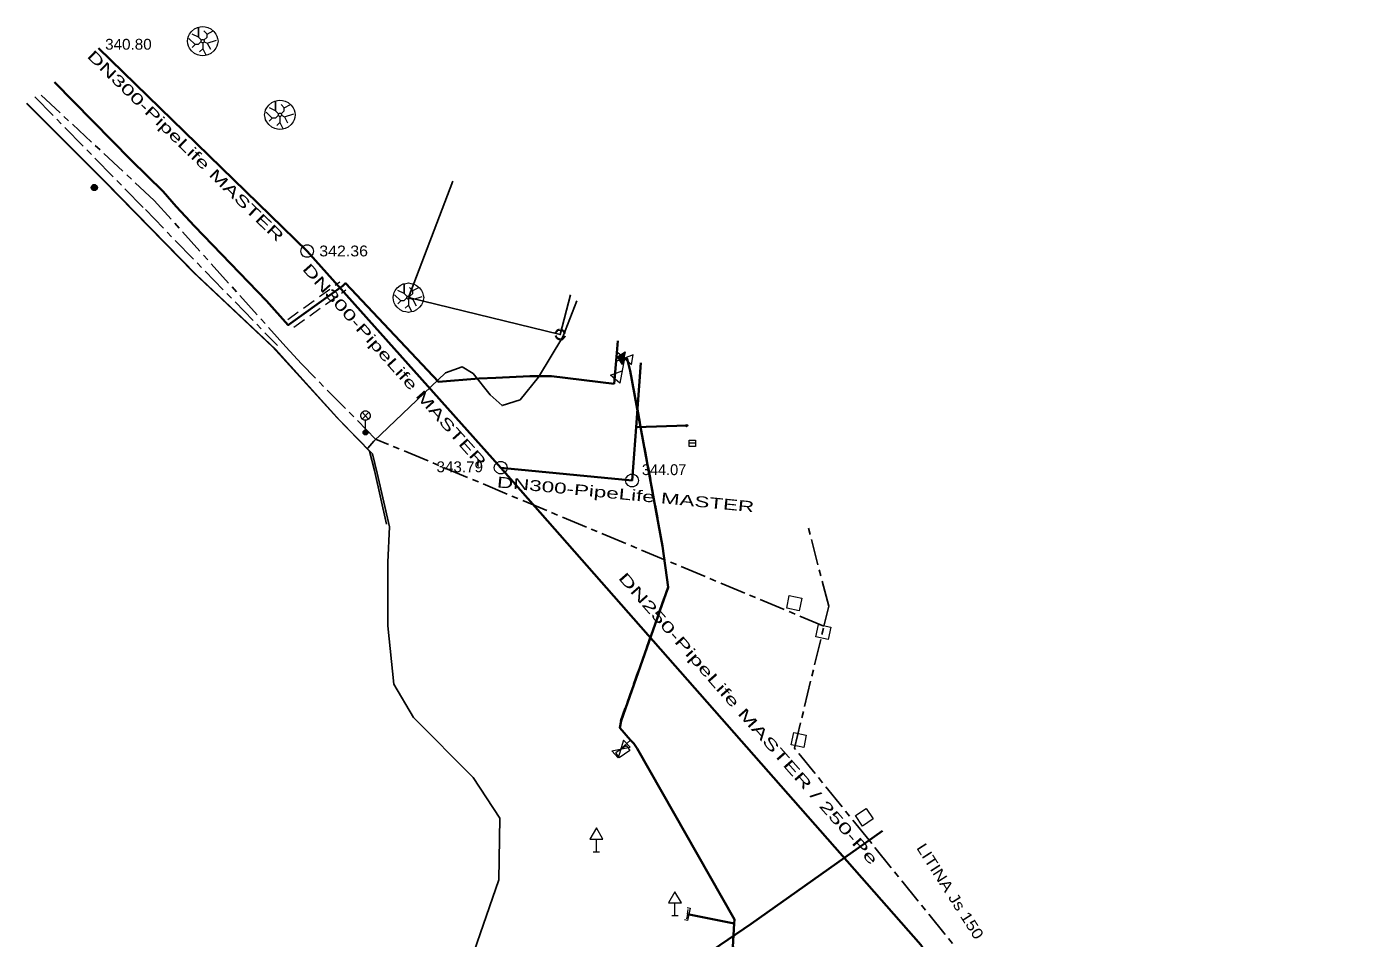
# Model space of a CAD drawing. Extents: x -763495 to -763378, y -1031793 to -1031652.
# Drawn here: x -763495.2 to -763391.6, y -1031723.9 to -1031652.3 of the extents above; entities that cross this region are included whole.
import ezdxf
from ezdxf.enums import TextEntityAlignment as Align

# ---------------------------------------------------------------- set-up
doc = ezdxf.new("R2010")
doc.units = 0
doc.header["$LTSCALE"] = 0.34
doc.linetypes.add('LONG_DASH_SHORT_DASH', pattern=[9.9, 6, -1.2, 1.5, -1.2])
doc.linetypes.add('MEDIUM_DASHED', pattern=[4.5, 3, -1.5])
for name, color, linetype, lineweight in [('23', 7, 'Continuous', 13), ('27', 7, 'Continuous', 13), ('33', 7, 'Continuous', 13), ('34', 7, 'Continuous', 13), ('35', 7, 'Continuous', 13), ('37', 7, 'Continuous', 13), ('40', 7, 'Continuous', 13), ('41', 7, 'Continuous', 13), ('43', 7, 'Continuous', 25), ('44', 7, 'Continuous', 35), ('45', 7, 'Continuous', 13), ('48', 7, 'Continuous', 25), ('51', 7, 'LONG_DASH_SHORT_DASH', 25), ('53', 7, 'Continuous', 25)]:
    doc.layers.add(name, color=color, linetype=linetype, lineweight=lineweight)

msp = doc.modelspace()

# ---------------------------------------------------------------- linework, layer by layer
at = {"layer": '23'}
for p, q in [((-763450.74, -1031717.13), (-763450.24, -1031717.13)), ((-763444.57, -1031722.14), (-763444.07, -1031722.14))]:
    msp.add_line(p, q, dxfattribs=at)
for points in [[(-763450.49, -1031717.13), (-763450.49, -1031716.13), (-763449.99, -1031716.13), (-763450.49, -1031715.255), (-763450.99, -1031716.13), (-763450.49, -1031716.13)], [(-763444.32, -1031722.14), (-763444.32, -1031721.14), (-763443.82, -1031721.14), (-763444.32, -1031720.265), (-763444.82, -1031721.14), (-763444.32, -1031721.14)]]:
    msp.add_lwpolyline(points, dxfattribs=at)
at = {"layer": '27'}
for p, q in [((-763481.04, -1031652.94), (-763481.28, -1031652.7)), ((-763481.98, -1031653.76), (-763482.22, -1031654)), ((-763481.38, -1031654.1), (-763481.14, -1031654.58)), ((-763481.02, -1031653.66), (-763480.3, -1031653.42)), ((-763474.98, -1031658.72), (-763475.22, -1031658.48)), ((-763474.96, -1031659.44), (-763474.24, -1031659.2)), ((-763475.92, -1031659.54), (-763476.16, -1031659.78)), ((-763475.32, -1031659.88), (-763475.08, -1031660.36)), ((-763464.9, -1031673.07), (-763465.14, -1031672.83)), ((-763464.88, -1031673.79), (-763464.16, -1031673.55)), ((-763465.84, -1031673.89), (-763466.08, -1031674.13)), ((-763465.24, -1031674.23), (-763465, -1031674.71)), ((-763453.615, -1031676.44), (-763453.75, -1031676.38)), ((-763453.615, -1031676.62), (-763453.75, -1031676.68)), ((-763453.585, -1031676.38), (-763453.705, -1031676.305)), ((-763453.585, -1031676.68), (-763453.705, -1031676.755)), ((-763453.54, -1031676.32), (-763453.645, -1031676.215)), ((-763453.54, -1031676.74), (-763453.645, -1031676.845)), ((-763453.495, -1031676.275), (-763453.57, -1031676.14)), ((-763453.495, -1031676.785), (-763453.57, -1031676.92)), ((-763453.435, -1031676.245), (-763453.48, -1031676.095)), ((-763453.435, -1031676.815), (-763453.48, -1031676.965)), ((-763453.375, -1031676.23), (-763453.405, -1031676.08)), ((-763453.375, -1031676.83), (-763453.405, -1031676.98)), ((-763453.285, -1031676.23), (-763453.255, -1031676.08)), ((-763453.285, -1031676.83), (-763453.255, -1031676.98)), ((-763453.225, -1031676.245), (-763453.18, -1031676.095)), ((-763453.225, -1031676.815), (-763453.18, -1031676.965)), ((-763453.165, -1031676.275), (-763453.09, -1031676.14)), ((-763453.165, -1031676.785), (-763453.09, -1031676.92)), ((-763453.12, -1031676.32), (-763453.015, -1031676.215)), ((-763453.12, -1031676.74), (-763453.015, -1031676.845)), ((-763453.075, -1031676.38), (-763452.955, -1031676.305)), ((-763453.075, -1031676.68), (-763452.955, -1031676.755)), ((-763453.045, -1031676.44), (-763452.91, -1031676.38)), ((-763453.045, -1031676.62), (-763452.91, -1031676.68))]:
    msp.add_line(p, q, dxfattribs=at)
for points in [[(-763482.58, -1031653.5), (-763482.54, -1031653.3), (-763482.5, -1031653.1), (-763482.42, -1031652.94), (-763482.26, -1031652.74), (-763482.02, -1031652.54), (-763481.78, -1031652.42), (-763481.58, -1031652.38), (-763481.38, -1031652.34), (-763481.18, -1031652.38), (-763480.98, -1031652.42), (-763480.74, -1031652.54), (-763480.5, -1031652.74), (-763480.34, -1031652.94), (-763480.26, -1031653.1), (-763480.22, -1031653.3), (-763480.18, -1031653.5), (-763480.22, -1031653.7), (-763480.26, -1031653.9), (-763480.34, -1031654.06), (-763480.5, -1031654.26), (-763480.74, -1031654.46), (-763480.98, -1031654.58), (-763481.18, -1031654.62), (-763481.38, -1031654.66), (-763481.58, -1031654.62), (-763481.78, -1031654.58), (-763482.02, -1031654.46), (-763482.26, -1031654.26), (-763482.42, -1031654.06), (-763482.5, -1031653.9), (-763482.54, -1031653.7)], [(-763481.5, -1031653.5), (-763481.5, -1031653.46), (-763481.48, -1031653.42), (-763481.42, -1031653.38), (-763481.34, -1031653.38), (-763481.28, -1031653.42), (-763481.26, -1031653.46), (-763481.26, -1031653.54), (-763481.28, -1031653.58), (-763481.34, -1031653.62), (-763481.42, -1031653.62), (-763481.48, -1031653.58), (-763481.5, -1031653.54)], [(-763476.52, -1031659.28), (-763476.48, -1031659.08), (-763476.44, -1031658.88), (-763476.36, -1031658.72), (-763476.2, -1031658.52), (-763475.96, -1031658.32), (-763475.72, -1031658.2), (-763475.52, -1031658.16), (-763475.32, -1031658.12), (-763475.12, -1031658.16), (-763474.92, -1031658.2), (-763474.68, -1031658.32), (-763474.44, -1031658.52), (-763474.28, -1031658.72), (-763474.2, -1031658.88), (-763474.16, -1031659.08), (-763474.12, -1031659.28), (-763474.16, -1031659.48), (-763474.2, -1031659.68), (-763474.28, -1031659.84), (-763474.44, -1031660.04), (-763474.68, -1031660.24), (-763474.92, -1031660.36), (-763475.12, -1031660.4), (-763475.32, -1031660.44), (-763475.52, -1031660.4), (-763475.72, -1031660.36), (-763475.96, -1031660.24), (-763476.2, -1031660.04), (-763476.36, -1031659.84), (-763476.44, -1031659.68), (-763476.48, -1031659.48)], [(-763475.44, -1031659.28), (-763475.44, -1031659.24), (-763475.42, -1031659.2), (-763475.36, -1031659.16), (-763475.28, -1031659.16), (-763475.22, -1031659.2), (-763475.2, -1031659.24), (-763475.2, -1031659.32), (-763475.22, -1031659.36), (-763475.28, -1031659.4), (-763475.36, -1031659.4), (-763475.42, -1031659.36), (-763475.44, -1031659.32)], [(-763466.44, -1031673.63), (-763466.4, -1031673.43), (-763466.36, -1031673.23), (-763466.28, -1031673.07), (-763466.12, -1031672.87), (-763465.88, -1031672.67), (-763465.64, -1031672.55), (-763465.44, -1031672.51), (-763465.24, -1031672.47), (-763465.04, -1031672.51), (-763464.84, -1031672.55), (-763464.6, -1031672.67), (-763464.36, -1031672.87), (-763464.2, -1031673.07), (-763464.12, -1031673.23), (-763464.08, -1031673.43), (-763464.04, -1031673.63), (-763464.08, -1031673.83), (-763464.12, -1031674.03), (-763464.2, -1031674.19), (-763464.36, -1031674.39), (-763464.6, -1031674.59), (-763464.84, -1031674.71), (-763465.04, -1031674.75), (-763465.24, -1031674.79), (-763465.44, -1031674.75), (-763465.64, -1031674.71), (-763465.88, -1031674.59), (-763466.12, -1031674.39), (-763466.28, -1031674.19), (-763466.36, -1031674.03), (-763466.4, -1031673.83)], [(-763465.36, -1031673.63), (-763465.36, -1031673.59), (-763465.34, -1031673.55), (-763465.28, -1031673.51), (-763465.2, -1031673.51), (-763465.14, -1031673.55), (-763465.12, -1031673.59), (-763465.12, -1031673.67), (-763465.14, -1031673.71), (-763465.2, -1031673.75), (-763465.28, -1031673.75), (-763465.34, -1031673.71), (-763465.36, -1031673.67)]]:
    msp.add_lwpolyline(points, close=True, dxfattribs=at)
for points in [[(-763481.48, -1031653.42), (-763481.72, -1031653.18), (-763481.72, -1031652.46), (-763481.72, -1031653.18), (-763482.2, -1031652.94)], [(-763481.28, -1031653.42), (-763481.04, -1031653.18), (-763481.04, -1031652.94), (-763480.56, -1031652.7)], [(-763481.5, -1031653.52), (-763481.74, -1031653.76), (-763481.98, -1031653.76), (-763482.46, -1031653.28)], [(-763481.38, -1031653.62), (-763481.38, -1031654.1), (-763481.62, -1031654.34)], [(-763481.26, -1031653.54), (-763481.02, -1031653.66), (-763480.78, -1031654.14)], [(-763475.42, -1031659.2), (-763475.66, -1031658.96), (-763475.66, -1031658.24), (-763475.66, -1031658.96), (-763476.14, -1031658.72)], [(-763475.44, -1031659.3), (-763475.68, -1031659.54), (-763475.92, -1031659.54), (-763476.4, -1031659.06)], [(-763475.22, -1031659.2), (-763474.98, -1031658.96), (-763474.98, -1031658.72), (-763474.5, -1031658.48)], [(-763475.2, -1031659.32), (-763474.96, -1031659.44), (-763474.72, -1031659.92)], [(-763475.32, -1031659.4), (-763475.32, -1031659.88), (-763475.56, -1031660.12)], [(-763465.34, -1031673.55), (-763465.58, -1031673.31), (-763465.58, -1031672.59), (-763465.58, -1031673.31), (-763466.06, -1031673.07)], [(-763465.36, -1031673.65), (-763465.6, -1031673.89), (-763465.84, -1031673.89), (-763466.32, -1031673.41)], [(-763465.24, -1031673.75), (-763465.24, -1031674.23), (-763465.48, -1031674.47)], [(-763465.14, -1031673.55), (-763464.9, -1031673.31), (-763464.9, -1031673.07), (-763464.42, -1031672.83)], [(-763465.12, -1031673.67), (-763464.88, -1031673.79), (-763464.64, -1031674.27)], [(-763453.345, -1031676.53), (-763453.315, -1031676.53), (-763453.33, -1031676.53)]]:
    msp.add_lwpolyline(points, dxfattribs=at)
at = {"layer": '27', "lineweight": 25}
msp.add_lwpolyline([(-763452.509, -1031673.421), (-763453.33, -1031676.53), (-763465.24, -1031673.63), (-763461.749, -1031664.479)], dxfattribs=at)
at = {"layer": '33'}
for points in [[(-763435.556, -1031698.001), (-763435.35, -1031697.023), (-763434.371, -1031697.229), (-763434.578, -1031698.207)], [(-763433.275, -1031700.265), (-763433.068, -1031699.286), (-763432.09, -1031699.493), (-763432.296, -1031700.471)], [(-763435.2, -1031708.737), (-763434.993, -1031707.758), (-763434.015, -1031707.965), (-763434.221, -1031708.943)], [(-763430.16, -1031714.277), (-763429.327, -1031713.724), (-763428.774, -1031714.556), (-763429.606, -1031715.11)]]:
    msp.add_lwpolyline(points, close=True, dxfattribs=at)
at = {"layer": '34'}
for points in [[(-763473.074, -1031669.495), (-763472.874, -1031669.59), (-763472.734, -1031669.765), (-763472.684, -1031669.98), (-763472.734, -1031670.195), (-763472.874, -1031670.37), (-763473.074, -1031670.465), (-763473.299, -1031670.465), (-763473.499, -1031670.37), (-763473.639, -1031670.195), (-763473.689, -1031669.98), (-763473.639, -1031669.765), (-763473.499, -1031669.59), (-763473.299, -1031669.495)], [(-763443.473, -1031683.621), (-763443.395, -1031683.582), (-763443.323, -1031683.633), (-763443.331, -1031683.723), (-763443.409, -1031683.762), (-763443.48, -1031683.711)], [(-763457.885, -1031686.496), (-763457.685, -1031686.591), (-763457.545, -1031686.766), (-763457.495, -1031686.981), (-763457.545, -1031687.196), (-763457.685, -1031687.371), (-763457.885, -1031687.466), (-763458.11, -1031687.466), (-763458.31, -1031687.371), (-763458.45, -1031687.196), (-763458.5, -1031686.981), (-763458.45, -1031686.766), (-763458.31, -1031686.591), (-763458.11, -1031686.496)], [(-763447.576, -1031687.501), (-763447.376, -1031687.596), (-763447.236, -1031687.771), (-763447.186, -1031687.986), (-763447.236, -1031688.201), (-763447.376, -1031688.376), (-763447.576, -1031688.471), (-763447.801, -1031688.471), (-763448.001, -1031688.376), (-763448.141, -1031688.201), (-763448.191, -1031687.986), (-763448.141, -1031687.771), (-763448.001, -1031687.596), (-763447.801, -1031687.501)]]:
    msp.add_lwpolyline(points, close=True, dxfattribs=at)
at = {"layer": '35'}
for points in [[(-763447.738, -1031678.869), (-763447.603, -1031678.131), (-763448.967, -1031678.643), (-763448.832, -1031677.905)], [(-763447.845, -1031708.914), (-763448.351, -1031708.361), (-763448.767, -1031709.759), (-763449.273, -1031709.206)]]:
    msp.add_lwpolyline(points, close=True, dxfattribs=at)
msp.add_lwpolyline([(-763448.285, -1031678.387), (-763448.646, -1031680.354), (-763449.392, -1031679.709), (-763448.466, -1031679.371)], dxfattribs=at)
at = {"layer": '37'}
msp.add_lwpolyline([(-763489.965, -1031664.76), (-763489.81, -1031664.76), (-763489.685, -1031664.85), (-763489.635, -1031664.995), (-763489.685, -1031665.14), (-763489.81, -1031665.23), (-763489.965, -1031665.23), (-763490.09, -1031665.14), (-763490.14, -1031664.995), (-763490.09, -1031664.85), (-763489.965, -1031664.76), (-763489.95, -1031664.78), (-763489.83, -1031664.78), (-763489.75, -1031664.82), (-763490.03, -1031664.82), (-763490.07, -1031664.86), (-763489.71, -1031664.86), (-763489.71, -1031664.9), (-763490.07, -1031664.9), (-763490.09, -1031664.94), (-763489.69, -1031664.94), (-763489.67, -1031664.98), (-763490.11, -1031664.98), (-763490.11, -1031665.02), (-763489.67, -1031665.02), (-763489.685, -1031665.06), (-763490.09, -1031665.06), (-763490.085, -1031665.1), (-763489.68, -1031665.1), (-763489.705, -1031665.14), (-763490.065, -1031665.14), (-763490.025, -1031665.18), (-763489.745, -1031665.18), (-763489.8, -1031665.22), (-763489.97, -1031665.22)], dxfattribs=at)
at = {"layer": '40'}
for p, q in [((-763468.36, -1031683.17), (-763468.875, -1031682.63)), ((-763468.87, -1031683.16), (-763468.345, -1031682.63))]:
    msp.add_line(p, q, dxfattribs=at)
for points in [[(-763468.615, -1031684.035), (-763468.615, -1031683.4), (-763468.615, -1031683.255), (-763468.71, -1031683.255), (-763468.875, -1031683.16), (-763468.975, -1031682.99), (-763468.975, -1031682.795), (-763468.88, -1031682.625), (-763468.71, -1031682.53), (-763468.515, -1031682.53), (-763468.345, -1031682.625), (-763468.25, -1031682.795), (-763468.25, -1031682.99), (-763468.36, -1031683.17), (-763468.515, -1031683.255), (-763468.61, -1031683.255)], [(-763468.61, -1031684.035), (-763468.535, -1031684.035), (-763468.425, -1031684.145), (-763468.425, -1031684.3), (-763468.535, -1031684.41), (-763468.69, -1031684.41), (-763468.8, -1031684.3), (-763468.8, -1031684.145), (-763468.69, -1031684.035), (-763468.615, -1031684.035), (-763468.54, -1031684.055), (-763468.69, -1031684.055), (-763468.72, -1031684.08), (-763468.52, -1031684.08), (-763468.48, -1031684.12), (-763468.76, -1031684.12), (-763468.78, -1031684.16), (-763468.455, -1031684.16), (-763468.455, -1031684.2), (-763468.78, -1031684.2), (-763468.78, -1031684.24), (-763468.455, -1031684.24), (-763468.455, -1031684.28), (-763468.775, -1031684.28), (-763468.755, -1031684.32), (-763468.475, -1031684.32), (-763468.515, -1031684.36), (-763468.715, -1031684.36), (-763468.69, -1031684.38), (-763468.535, -1031684.38)]]:
    msp.add_lwpolyline(points, dxfattribs=at)
at = {"layer": '41'}
msp.add_lwpolyline([(-763442.72, -1031685.06), (-763442.72, -1031685.31), (-763443.22, -1031685.31), (-763443.22, -1031684.81), (-763442.72, -1031684.81), (-763442.72, -1031685.06), (-763443.22, -1031685.06)], dxfattribs=at)
at = {"layer": '43', "linetype": 'LONG_DASH_SHORT_DASH'}
for points in [[(-763410.479, -1031739.762), (-763410.419, -1031739.329), (-763429.088, -1031716.231), (-763434.935, -1031708.998), (-763432.635, -1031699.413), (-763467.811, -1031684.74), (-763473.63, -1031678.84), (-763474.846, -1031677.495), (-763485.18, -1031666.004), (-763494.195, -1031657.611)], [(-763432.635, -1031699.413), (-763432.255, -1031697.852), (-763433.93, -1031691.402)]]:
    msp.add_lwpolyline(points, dxfattribs=at)
at = {"layer": '43', "lineweight": 35}
msp.add_lwpolyline([(-763428.03, -1031715.48), (-763438.34, -1031722.78), (-763475.986, -1031748.441)], dxfattribs=at)
at = {"layer": '44'}
msp.add_line((-763443.402, -1031683.672), (-763447.378, -1031683.808), dxfattribs=at)
for points in [[(-763457.995, -1031686.981), (-763473.184, -1031669.98), (-763489.553, -1031654.06)], [(-763447.005, -1031678.748), (-763447.378, -1031683.808), (-763447.686, -1031687.986), (-763457.995, -1031686.981)], [(-763391.618, -1031789.234), (-763393.492, -1031784.483), (-763400.133, -1031767.646), (-763400.737, -1031766.222), (-763405.172, -1031755.763), (-763407.519, -1031750.23), (-763407.897, -1031749.337), (-763411.012, -1031744.81), (-763417.435, -1031735.477), (-763425.031, -1031724.437), (-763457.995, -1031686.981)]]:
    msp.add_lwpolyline(points, dxfattribs=at)
at = {"layer": '45', "linetype": 'MEDIUM_DASHED'}
for p, q in [((-763474.704, -1031675.347), (-763470.615, -1031672.388)), ((-763474.474, -1031675.633), (-763470.383, -1031672.702)), ((-763474.223, -1031675.947), (-763470.146, -1031673.022)), ((-763447.879, -1031679.397), (-763445.339, -1031693.147)), ((-763447.84, -1031679.39), (-763445.3, -1031693.14)), ((-763447.801, -1031679.383), (-763445.261, -1031693.133)), ((-763448.588, -1031706.827), (-763444.887, -1031696.347)), ((-763448.55, -1031706.84), (-763444.849, -1031696.36)), ((-763448.512, -1031706.853), (-763444.811, -1031696.373))]:
    msp.add_line(p, q, dxfattribs=at)
at = {"layer": '45', "lineweight": 35}
for p, q in [((-763448.909, -1031678.28), (-763448.795, -1031677.015)), ((-763449.1, -1031680.39), (-763448.909, -1031678.28)), ((-763443.35, -1031722.02), (-763439.677, -1031722.759))]:
    msp.add_line(p, q, dxfattribs=at)
at = {"layer": '45', "lineweight": 25}
msp.add_line((-763447.81, -1031708.37), (-763448.559, -1031709.06), dxfattribs=at)
at = {"layer": '45'}
for q in [(-763443.425, -1031722.388), (-763443.275, -1031721.652)]:
    msp.add_line((-763443.35, -1031722.02), q, dxfattribs=at)
at = {"layer": '45', "lineweight": 35}
for points in [[(-763493.013, -1031656.707), (-763486.99, -1031662.84), (-763484.47, -1031665.3), (-763483.46, -1031666.48), (-763482.73, -1031667.26), (-763482.02, -1031668.02), (-763476.37, -1031673.88), (-763474.67, -1031675.79), (-763474.47, -1031675.63), (-763470.383, -1031672.702), (-763470.17, -1031672.5), (-763462.89, -1031680.24), (-763459.7, -1031679.97), (-763458.38, -1031679.94), (-763455.7, -1031679.8), (-763454, -1031679.8), (-763449.1, -1031680.39)], [(-763448.587, -1031678.33), (-763448.597, -1031678.328), (-763448.857, -1031678.285), (-763448.909, -1031678.28)], [(-763439.677, -1031722.759), (-763439.66, -1031722.45), (-763447.3, -1031709.02), (-763447.56, -1031708.63), (-763447.81, -1031708.37), (-763448.65, -1031707.4), (-763448.55, -1031706.84), (-763444.849, -1031696.36), (-763445.3, -1031693.14), (-763447.84, -1031679.39), (-763448.072, -1031678.425), (-763448.285, -1031678.387), (-763448.587, -1031678.33)], [(-763414.95, -1031744.87), (-763415.97, -1031743.05), (-763420.26, -1031739.42), (-763424.39, -1031735.42), (-763434.3, -1031728.54), (-763439.78, -1031724.58), (-763439.677, -1031722.759)]]:
    msp.add_lwpolyline(points, dxfattribs=at)
at = {"layer": '45'}
for points in [[(-763448.442, -1031678.87), (-763448.832, -1031678.28), (-763448.242, -1031677.89), (-763448.369, -1031678.512), (-763448.442, -1031678.87), (-763448.459, -1031678.8), (-763448.331, -1031678.178), (-763448.283, -1031677.943), (-763448.331, -1031677.974), (-763448.458, -1031678.596), (-763448.491, -1031678.758), (-763448.523, -1031678.716), (-763448.396, -1031678.093), (-763448.378, -1031678.005), (-763448.426, -1031678.041), (-763448.553, -1031678.664), (-763448.585, -1031678.621), (-763448.475, -1031678.082), (-763448.521, -1031678.109), (-763448.616, -1031678.574), (-763448.648, -1031678.527), (-763448.568, -1031678.135), (-763448.616, -1031678.171), (-763448.68, -1031678.485), (-763448.711, -1031678.437), (-763448.665, -1031678.212), (-763448.706, -1031678.239), (-763448.738, -1031678.396), (-763448.769, -1031678.349), (-763448.753, -1031678.27), (-763448.801, -1031678.302)], [(-763443.373, -1031721.505), (-763443.128, -1031721.555), (-763443.327, -1031722.535), (-763443.572, -1031722.485)]]:
    msp.add_lwpolyline(points, dxfattribs=at)
msp.add_lwpolyline([(-763448.559, -1031709.06), (-763448.147, -1031708.777), (-763447.864, -1031709.189), (-763448.688, -1031709.755), (-763448.971, -1031709.343)], close=True, dxfattribs=at)
at = {"layer": '48'}
for p, q in [((-763453.12, -1031676.72), (-763453.119, -1031676.72)), ((-763462.33, -1031679.54), (-763462.329, -1031679.54)), ((-763461.03, -1031679.07), (-763461.029, -1031679.07)), ((-763460.17, -1031679.58), (-763460.169, -1031679.58)), ((-763455.03, -1031679.88), (-763455.029, -1031679.88)), ((-763458.82, -1031681.25), (-763458.819, -1031681.25)), ((-763457.89, -1031682.1), (-763457.889, -1031682.1)), ((-763456.48, -1031681.65), (-763456.479, -1031681.65)), ((-763468.42, -1031685.45), (-763467.95, -1031684.91)), ((-763467.95, -1031684.91), (-763467.949, -1031684.91)), ((-763468.42, -1031685.45), (-763468.419, -1031685.45))]:
    msp.add_line(p, q, dxfattribs=at)
for points in [[(-763495.215, -1031658.392), (-763489.14, -1031664.47), (-763482.1, -1031671.65), (-763475.9, -1031677.49), (-763470.84, -1031683.08), (-763468.28, -1031685.69), (-763467.9, -1031687.2), (-763466.95, -1031691.41)], [(-763495.174, -1031658.36), (-763488.91, -1031664.64), (-763481.87, -1031671.83)], [(-763481.87, -1031671.83), (-763475.67, -1031677.68), (-763470.62, -1031683.28), (-763468.06, -1031685.9), (-763467.68, -1031687.41), (-763466.73, -1031691.62), (-763466.86, -1031694.4), (-763466.86, -1031699.4)], [(-763467.95, -1031684.91), (-763462.33, -1031679.54), (-763461.03, -1031679.07), (-763460.17, -1031679.58), (-763458.82, -1031681.25), (-763457.89, -1031682.1), (-763456.48, -1031681.65), (-763455.03, -1031679.88), (-763453.12, -1031676.72), (-763452.034, -1031673.881)], [(-763466.86, -1031699.4), (-763466.38, -1031703.98), (-763464.85, -1031706.59), (-763460.17, -1031711.3), (-763458.07, -1031714.49), (-763458.15, -1031719.33)], [(-763458.15, -1031719.33), (-763461.3, -1031728.5), (-763464.77, -1031734.06), (-763466.7, -1031735.67), (-763473.81, -1031738.85), (-763479.899, -1031740.933)]]:
    msp.add_lwpolyline(points, dxfattribs=at)
at = {"layer": '51'}
msp.add_lwpolyline([(-763494.544, -1031657.878), (-763485.879, -1031666.726), (-763475.506, -1031677.401)], dxfattribs=at)
at = {"layer": '53'}
msp.add_lwpolyline([(-763495.174, -1031658.36), (-763488.91, -1031664.64), (-763481.87, -1031671.83), (-763475.67, -1031677.68), (-763470.62, -1031683.28), (-763468.06, -1031685.9), (-763467.68, -1031687.41), (-763466.73, -1031691.62), (-763466.86, -1031694.4), (-763466.86, -1031699.4), (-763466.38, -1031703.98), (-763464.85, -1031706.59), (-763460.17, -1031711.3), (-763458.07, -1031714.49), (-763458.15, -1031719.33), (-763461.3, -1031728.5), (-763464.77, -1031734.06), (-763466.7, -1031735.67), (-763473.81, -1031738.85), (-763479.899, -1031740.933)], dxfattribs=at)

# ---------------------------------------------------------------- texts
at = {"layer": '33', "width": 1.2}
msp.add_text('LITINA Js 150', height=0.85, rotation=302.579, dxfattribs=at).set_placement((-763423.083, -1031720.459), align=Align.CENTER)
at = {"layer": '44'}
for s, width, p in [('340.80', 1.05, (-763487.211, -1031654.168)), ('342.36', 1.1, (-763470.322, -1031670.395)), ('343.79', 1.05, (-763461.209, -1031687.337))]:
    msp.add_text(s, height=0.85, dxfattribs=dict(at, width=width)).set_placement(p, align=Align.CENTER)
for s, rotation, width, p in [('DN300-PipeLife MASTER', 315.825, 1.6, (-763483.017, -1031662.026)), ('DN300-PipeLife MASTER', 311.757, 1.6, (-763466.648, -1031679.221)), ('DN300-PipeLife MASTER', 354.442, 1.55, (-763448.236, -1031689.499)), ('DN250-PipeLife MASTER / 250-Pe', 311.356, 1.7, (-763438.884, -1031706.95))]:
    msp.add_text(s, height=0.85, rotation=rotation, dxfattribs=dict(at, width=width)).set_placement(p, align=Align.CENTER)
msp.add_text('344.07', height=0.85, dxfattribs=at).set_placement((-763445.175, -1031687.562), align=Align.CENTER)

doc.saveas('drawing.dxf')
